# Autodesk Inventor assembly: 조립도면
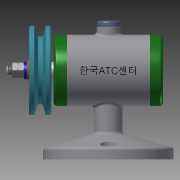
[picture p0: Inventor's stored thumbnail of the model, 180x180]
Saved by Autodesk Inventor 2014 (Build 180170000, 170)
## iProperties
Created: 2018-12
Part Number: 조립도면
Document SubType Name: Assembly
Designer: kh
Author: kh
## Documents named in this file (15)
- C:\Users\kh\Desktop\481207V1033\조립도면.iam
- C:\Users\kh\Desktop\481207V1033\본체.ipt
- C:\Users\kh\Desktop\481207V1033\V벨트풀리.ipt
- C:\Users\kh\Desktop\481207V1033\고무캡.ipt
- C:\Users\kh\Desktop\481207V1033\너트 M8.ipt
- 너트 M8.ipt
- C:\Users\kh\Desktop\481207V1033\뒤커버.ipt
- C:\Users\kh\Desktop\481207V1033\베어링 15 x 32 x 9.ipt
- C:\Users\kh\Desktop\481207V1033\볼트 M4 x 12.ipt
- C:\Users\kh\Desktop\481207V1033\스프링와셔 8.ipt
- C:\Users\kh\Desktop\481207V1033\앞커버.ipt
- C:\Users\kh\Desktop\481207V1033\오일 실 15 25 7.ipt
- C:\Users\kh\Desktop\481207V1033\와셔 8x17.ipt
- C:\Users\kh\Desktop\481207V1033\축.ipt
- C:\Users\kh\Desktop\481207V1033\키 3 x 3 x 12.ipt
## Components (2 placed, 2 different names)
1. V벨트풀리:1 — Insert:4, Mate:1, Insert:5
2. 고무캡:1 — Insert:18, Angle:1, Angle:2, Angle:3, Angle:4, Angle:5, Angle:6, Angle:7, Angle:8, Angle:9, Angle:10, Angle:11
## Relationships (15: Angle 11, Insert 3, Mate 1)
- Insert:4: V벨트풀리:1
- Mate:1: V벨트풀리:1
- Insert:5: V벨트풀리:1
- Insert:18: 고무캡:1
- Angle:1: 고무캡:1
- Angle:2: 고무캡:1
- Angle:3: 고무캡:1
- Angle:4: 고무캡:1
- Angle:5: 고무캡:1
- Angle:6: 고무캡:1
- Angle:7: 고무캡:1
- Angle:8: 고무캡:1
- Angle:9: 고무캡:1
- Angle:10: 고무캡:1
- Angle:11: 고무캡:1
